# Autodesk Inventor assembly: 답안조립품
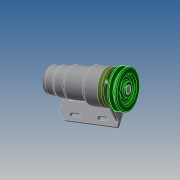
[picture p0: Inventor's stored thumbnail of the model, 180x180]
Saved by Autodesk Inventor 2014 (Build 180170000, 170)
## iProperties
Created: 2017-09
Part Number: 답안조립품
Document SubType Name: Assembly
Designer: kb542-27
Author: kb542-27
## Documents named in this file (12)
- C:\Users\kb542-27\Desktop\470907V1012\답안조립품.iam
- C:\Users\kb542-27\Desktop\470907V1012\1-본체.ipt
- C:\Users\kb542-27\Desktop\470907V1012\V벨트풀리.ipt
- C:\Users\kb542-27\Desktop\470907V1012\멈춤나사 M3x8.ipt
- C:\Users\kb542-27\Desktop\470907V1012\베어링 6004.ipt
- C:\Users\kb542-27\Desktop\470907V1012\베어링 51202.ipt
- C:\Users\kb542-27\Desktop\470907V1012\볼트 M4 x 12.ipt
- C:\Users\kb542-27\Desktop\470907V1012\어댑터슬리브.ipt
- C:\Users\kb542-27\Desktop\470907V1012\오일 실 20x35x7.ipt
- C:\Users\kb542-27\Desktop\470907V1012\축.ipt
- C:\Users\kb542-27\Desktop\470907V1012\커버.ipt
- C:\Users\kb542-27\Desktop\470907V1012\키 5 x 5 x 16.ipt
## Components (2 placed, 2 different names)
1. 1-본체:1
2. V벨트풀리:1
